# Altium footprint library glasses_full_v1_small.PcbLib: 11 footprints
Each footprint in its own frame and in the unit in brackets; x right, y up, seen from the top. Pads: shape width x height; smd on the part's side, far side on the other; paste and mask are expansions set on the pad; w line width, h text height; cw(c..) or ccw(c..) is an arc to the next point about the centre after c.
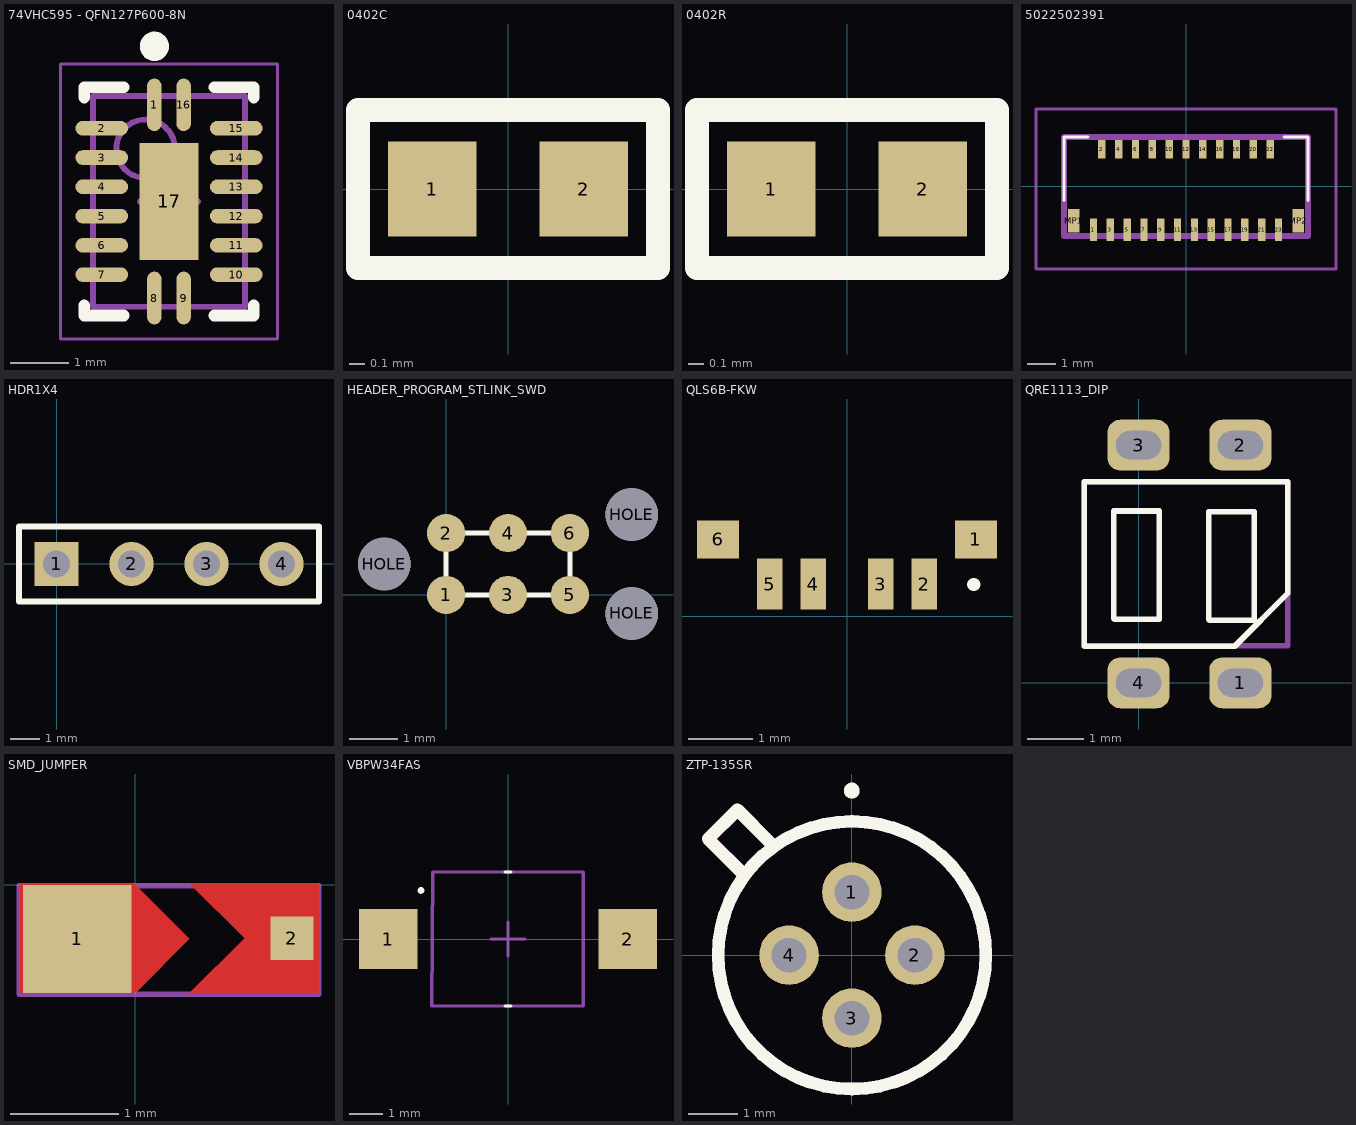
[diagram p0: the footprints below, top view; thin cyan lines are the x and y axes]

## 74VHC595 - QFN127P600-8N [mm]
height 1
pads (17):
  oval 0.25x0.9 smd: 1(-1159.523,-1185.292) 8(-1159.523,-1188.592) 9(-1159.023,-1188.592) 16(-1159.023,-1185.292)
  oval 0.9x0.25 smd: 2(-1160.423,-1185.692) 3(-1160.423,-1186.192) 4(-1160.423,-1186.692) 5(-1160.423,-1187.192) 6(-1160.423,-1187.692) 7(-1160.423,-1188.192) 10(-1158.123,-1188.192) 11(-1158.123,-1187.692) 12(-1158.123,-1187.192) 13(-1158.123,-1186.692) 14(-1158.123,-1186.192) 15(-1158.123,-1185.692)
  rect 1x2 smd: 17(-1159.273,-1186.942)
Top Overlay:
  circle w0.25: c-1159.523,-1184.292 r0.125
  lines w0.2: -1160.723,-1188.717 -1160.723,-1188.892 -1160.048,-1188.892 ; -1160.723,-1185.167 -1160.723,-1184.992 -1160.048,-1184.992 ; -1158.498,-1188.892 -1157.823,-1188.892 -1157.823,-1188.717 ; -1158.498,-1184.992 -1157.823,-1184.992 -1157.823,-1185.167
Mechanical 13:
  circle w0.1: c-1159.673,-1186.042 r0.5
  lines w0.1: -1160.573,-1188.742 -1157.973,-1188.742 -1157.973,-1185.142 -1160.573,-1185.142 -1160.573,-1188.742
Mechanical 15:
  lines w0.05: -1161.123,-1189.292 -1157.423,-1189.292 -1157.423,-1184.592 -1161.123,-1184.592 -1161.123,-1189.292
  lines w0.1: -1159.773,-1186.942 -1158.773,-1186.942 ; -1159.273,-1187.442 -1159.273,-1186.442
3D body: height 1, standoff 0, extent -1160.573,-1188.742 -1157.973,-1185.142

## 0402C [mm]
pads (2):
  rect 0.559x0.6 smd: 1(-0.48,0) 2(0.48,0)
Top Overlay:
  lines w0.152: -0.95,-0.5 0.95,-0.5 0.95,0.5 -0.95,0.5 -0.95,-0.5
3D body: height 0.5, standoff 0, extent -0.483,-0.254 0.477,0.246

## 0402R [mm]
pads (2):
  rect 0.559x0.6 smd: 1(-0.48,0) 2(0.48,0)
Top Overlay:
  lines w0.152: -0.95,-0.5 0.95,-0.5 0.95,0.5 -0.95,0.5 -0.95,-0.5
3D body: height 0.3, standoff 0, extent -0.457,-0.254 0.503,0.246

## 5022502391 [mm]
pads (25):
  rect 0.26x0.8 smd: 1(-3.3,-1.545) 3(-2.7,-1.545) 5(-2.1,-1.545) 7(-1.5,-1.545) 9(-0.9,-1.545) 11(-0.3,-1.545) 13(0.3,-1.545) 15(0.9,-1.545) 17(1.5,-1.545) 19(2.1,-1.545) 21(2.7,-1.545) 23(3.3,-1.545)
  rect 0.26x0.65 smd: 2(-3,1.33) 4(-2.4,1.33) 6(-1.8,1.33) 8(-1.2,1.33) 10(-0.6,1.33) 12(0,1.33) 14(0.6,1.33) 16(1.2,1.33) 18(1.8,1.33) 20(2.4,1.33) 22(3,1.33)
  rect 0.4x0.85 smd: MP1(-4,-1.22) MP2(4,-1.22)
Top Overlay:
  lines w0.1: -4.35,-0.5 -4.35,1.765 -3.5,1.765 ; 3.5,1.765 4.35,1.765 4.35,-0.5
Mechanical 13:
  lines w0.2: -4.35,-1.765 -4.35,1.765 4.35,1.765 4.35,-1.765 -4.35,-1.765
Mechanical 15:
  lines w0.1: -5.35,-2.945 -5.35,2.765 5.35,2.765 5.35,-2.945 -5.35,-2.945
3D body: height 0.9, standoff 0, extent -4.35,-1.765 4.35,2.425

## HDR1X4 [mm] "Connector; Header; 4 Position"
pads (4):
  rect 1.5x1.5 hole 0.9: 1(0,0)
  round 1.5 hole 0.9: 2(2.54,0) 3(5.08,0) 4(7.62,0)
Top Overlay:
  lines w0.2: -1.27,-1.27 8.89,-1.27 8.89,1.27 -1.27,1.27 -1.27,-1.27

## HEADER_PROGRAM_STLINK_SWD [mm]
pads (9):
  round 0.787 smd: 1(0,0) 2(0,1.27) 3(1.27,0) 4(1.27,1.27) 5(2.54,0) 6(2.54,1.27)
  round 1.08 hole 1.08 unplated: HOLE(-1.27,0.635) HOLE(3.81,-0.381) HOLE(3.81,1.651)
Top Overlay:
  lines w0.1: 0,0 0,1.27 2.54,1.27 2.54,0 0,0

## QLS6B-FKW [mm] "CREE RBG LED RIGHT ANGLE"
height 1.3
pads (6):
  rect 0.66x0.6 smd: 1(2.02,1.2) 6(-2.02,1.2)
  rect 0.4x0.8 smd: 2(1.21,0.5) 3(0.53,0.5) 4(-0.53,0.5) 5(-1.21,0.5)
Top Overlay:
  lines w0.2: 1.981,0.494 1.991,0.494
3D body: height 1.3, standoff 0, extent -2.354,0.115 2.346,1.615

## QRE1113_DIP [mm] "QRE1113 IR PHOTODIODE/TRANSISTOR PAIR"
height 1.7
pads (4):
  rrect50% 1.1x0.9 hole 0.5 slot 0.8 at 0 deg: 1(1.8,0) 2(1.8,4.2) 3(0,4.2) 4(0,0)
Top Overlay:
  lines w0.1: 1.24,1.122 1.24,3.021 2.042,3.021 2.042,1.107 1.255,1.107 ; -0.961,0.653 -0.955,0.647 1.7,0.647 2.639,1.585 2.639,3.553 -0.961,3.553 -0.961,0.653 ; -0.436,1.136 -0.421,1.122 0.365,1.122 0.365,3.036 -0.436,3.036 -0.436,1.136
Mechanical 15:
  lines w0.1: -0.961,0.653 2.639,0.653 2.639,3.553 -0.961,3.553 -0.961,0.653

## SMD_JUMPER [mm]
height 1
pads (2):
  rect 1x1 smd: 1(-0.536,-0.5)
  rect 0.4x0.4 smd: 2(1.45,-0.494)
Top Layer:
  region: -1.061,0.01 -0.01,0.01 0.5,-0.5 0.01,-0.992 -1.061,-0.992
  region: 1.012,-0.494 0.504,0.01 1.7,0.01 1.7,-1.005 0.5,-1.005
Mechanical 15:
  lines w0.05: -1.074,-1.013 -1.074,-0.011 1.7,-0.011 1.7,-1.013 -1.074,-1.013

## VBPW34FAS [mm] "IR Photodiode SMD (Vive)"
height 1.3
pads (2):
  rect 1.75x1.8 smd: 1(-3.575,0) 2(3.575,0)
Top Overlay:
  circle w0.1: c-2.596,1.449 r0.05
  lines w0.1: -0.09,-2 0.081,-2 ; -0.09,2 0.081,2
Mechanical 13:
  lines w0.1: -2.273,-2 -2.25,2 2.25,2 2.25,-2 -2.25,-2
Mechanical 15:
  lines w0.05: -2.262,-2 2.244,-2 2.244,2 -2.262,2 -2.262,-2
  lines w0.1: -0.5,0 0.5,0 ; 0,-0.5 0,0.5
3D body: height 1.48, standoff -0.02, extent -3.29,-1.95 3.11,1.95

## ZTP-135SR [mm]
pads (4):
  round 1.2 hole 0.7: 1(0,1.27) 2(1.27,0) 3(0,-1.27) 4(-1.27,0)
Top Overlay:
  circle w0.254: c0,0 r2.7
  circle w0.254: c-0.005,3.32 r0.032
  lines w0.254: -2.166,1.612 -2.901,2.347 -2.314,2.934 -1.646,2.266
Mechanical 13:
  circle w0.254: c0,0 r2.7
  lines w0.254: -2.16,1.606 -2.828,2.274 -2.901,2.347 -2.314,2.934 -1.646,2.266
3D body: height 3.4, standoff -12.86, extent -4.428,-3.772 3.799,4.456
